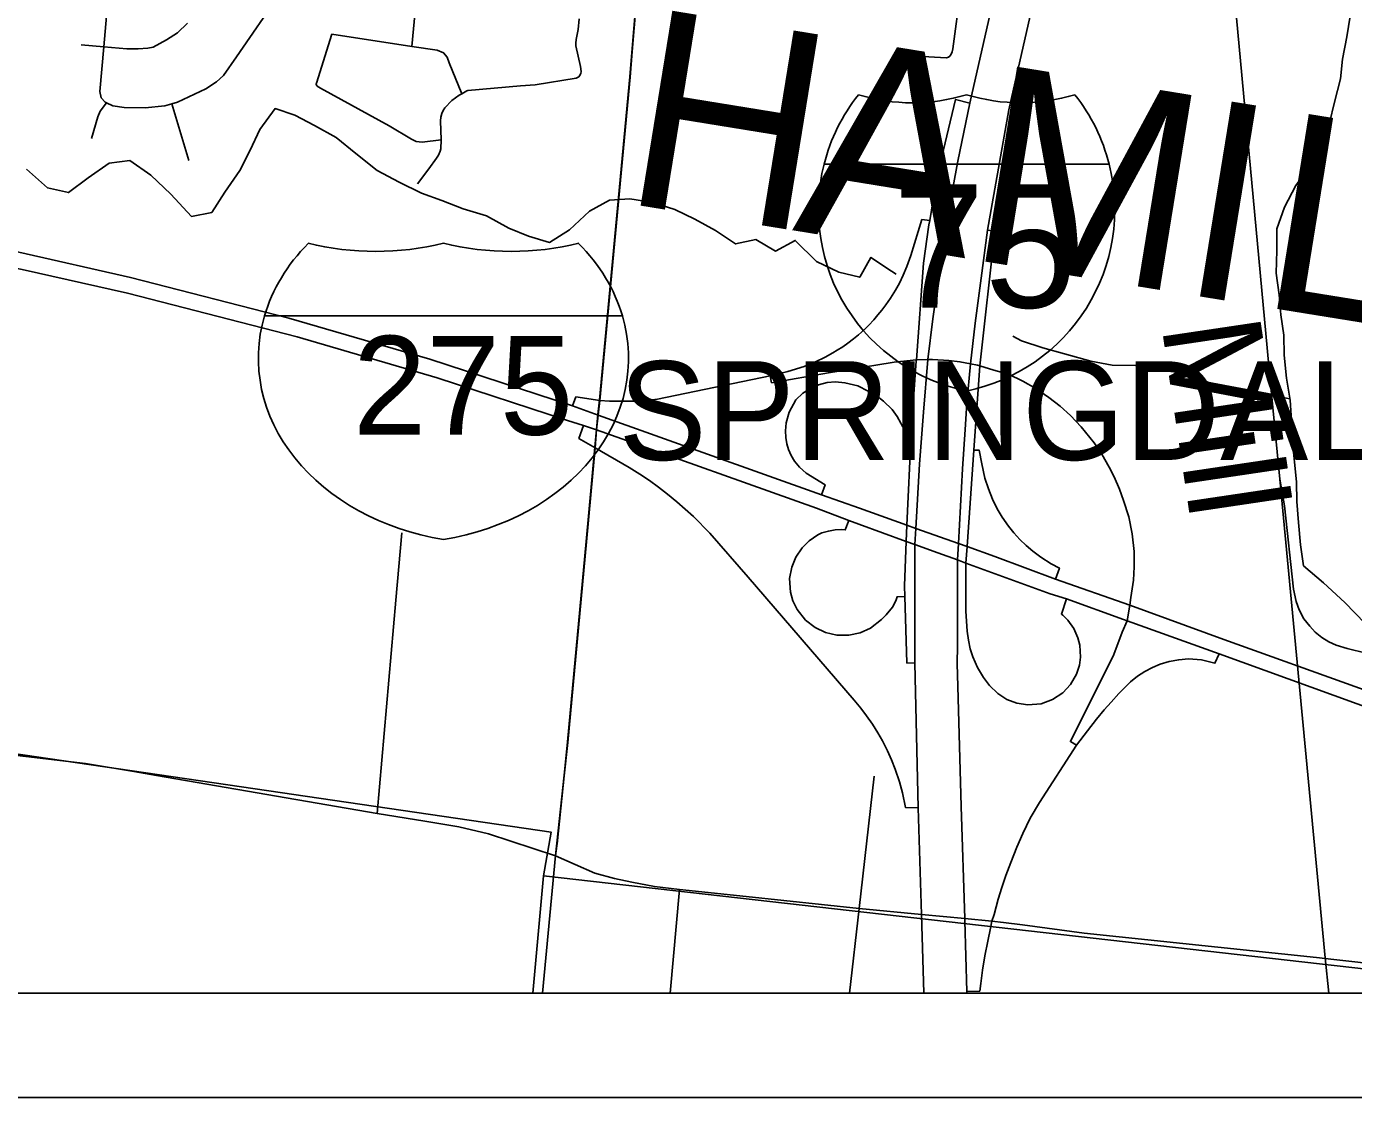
# Model space of a CAD drawing. Extents: x 0 to 34, y 0 to 22.
# Drawn here: x 4.792 to 6.065, y 14 to 15.027 of the extents above; entities that cross this region are included whole.
import ezdxf

# ---------------------------------------------------------------- set-up
doc = ezdxf.new("R2010")
doc.units = 0
for name, color, linetype in [('Default', 7, 'Continuous'), ('GM_X_City_Street', 7, 'Continuous'), ('GM_X_Corporation_Text', 7, 'Continuous'), ('GM_X_County_Road', 7, 'Continuous'), ('GM_X_County_Text', 7, 'Continuous'), ('GM_X_Interchange_Ramps', 7, 'Continuous'), ('GM_X_Interstate_Location', 7, 'Continuous'), ('GM_X_Interstate_Route', 7, 'Continuous'), ('GM_X_Interstate_Shield', 7, 'Continuous'), ('GM_X_Minor_River', 7, 'Continuous'), ('GM_X_Minor_River_Text', 7, 'Continuous'), ('GM_X_Rail_Line', 7, 'Continuous'), ('GM_X_Township_Road', 7, 'Continuous'), ('SH_Cut_Line', 7, 'Continuous'), ('SH_Data', 7, 'Continuous')]:
    doc.layers.add(name, color=color, linetype=linetype)

msp = doc.modelspace()

# ---------------------------------------------------------------- linework, layer by layer
at = {"layer": 'Default'}
for points in [[(4.2792, 14.1), (5.2778, 14.1), (5.2881, 14.2126), (5.2952, 14.2546), (4.3078, 14.3989)], [(5.2778, 14.1), (6.2802, 14.1), (5.2881, 14.2126)]]:
    msp.add_lwpolyline(points, close=True, dxfattribs=at)
at = {"layer": 'GM_X_City_Street'}
for p, q in [((4.9478, 14.8986), (4.9314, 14.9531)), ((5.5906, 14.1811), (5.6049, 14.3083)), ((5.2996, 14.2316), (5.3008, 14.2414)), ((5.4093, 14.1), (5.4184, 14.1996))]:
    msp.add_line(p, q, dxfattribs=at)
for points in [[(5.1618, 15.0081), (5.1671, 15.066), (5.1722, 15.1214), (5.1787, 15.1925), (5.1787, 15.1973), (5.1785, 15.2015), (5.1775, 15.2101), (5.1705, 15.2357), (5.1703, 15.237), (5.1706, 15.2403), (5.1711, 15.2453), (5.1719, 15.256), (5.1742, 15.2989)], [(5.3731, 15.0032), (5.3809, 15.0981), (5.3964, 15.26)], [(5.646, 14.9986), (5.6743, 14.9972), (5.6762, 14.9977), (5.6776, 14.9988), (5.6788, 15.0006), (5.6798, 15.003), (5.6805, 15.0059), (5.6879, 15.0612), (5.6884, 15.0649), (5.7015, 15.2083)], [(4.8817, 15.1847), (4.8662, 15.0077), (4.8625, 14.9647), (4.8637, 14.9589), (4.8677, 14.9546), (4.8689, 14.954), (4.8748, 14.9512), (4.8857, 14.9496), (4.9059, 14.9491), (4.9248, 14.9512), (4.9314, 14.9531), (4.9369, 14.9546), (4.964, 14.9675), (4.9744, 14.974), (4.9812, 14.9801), (4.9934, 14.9982), (5.0353, 15.0592)], [(4.8446, 15.0096), (4.8662, 15.0077), (4.8885, 15.0058), (4.8991, 15.0057), (4.9085, 15.0063), (4.9136, 15.0074), (4.9265, 15.0144), (4.937, 15.0212), (4.9467, 15.0305)], [(5.1671, 14.8763), (5.178, 14.8906), (5.1853, 14.901), (5.1873, 14.9039), (5.1888, 14.9075), (5.1895, 14.9099), (5.1898, 14.9186), (5.1891, 14.9366), (5.1895, 14.9401), (5.1905, 14.9437), (5.1918, 14.9466), (5.1934, 14.9493), (5.2002, 14.9562), (5.2072, 14.9612), (5.2096, 14.9627), (5.2143, 14.9656), (5.2154, 14.9658), (5.2659, 14.9702), (5.2798, 14.9714), (5.3193, 14.9775), (5.3217, 14.9789), (5.3225, 14.98), (5.3236, 14.9821), (5.324, 14.984), (5.3235, 14.9889), (5.319, 15.0085), (5.3189, 15.0112), (5.3193, 15.0146), (5.3212, 15.0244), (5.3222, 15.0346)], [(5.0851, 15.0197), (5.0702, 14.9729), (5.0701, 14.9721), (5.0701, 14.9715), (5.0705, 14.9706), (5.071, 14.97), (5.0742, 14.9681), (5.1399, 14.9318), (5.1614, 14.9191), (5.1658, 14.917), (5.1688, 14.9165), (5.1715, 14.9164), (5.1898, 14.9186)], [(5.2096, 14.9627), (5.1975, 14.9925), (5.1955, 14.9979), (5.1922, 15.0018), (5.1859, 15.0044), (5.1618, 15.0081), (5.0851, 15.0197)], [(5.3008, 14.2414), (5.301, 14.2434), (5.3079, 14.3086), (5.3112, 14.3404), (5.3291, 14.5328), (5.3374, 14.6232), (5.3389, 14.6402), (5.3404, 14.6544), (5.3419, 14.6686), (5.371, 14.9785), (5.3731, 15.0032)], [(4.8545, 14.9198), (4.8607, 14.9404), (4.8628, 14.946), (4.8689, 14.954)], [(5.1285, 14.2725), (5.1465, 14.4771), (5.1521, 14.5415)]]:
    msp.add_lwpolyline(points, dxfattribs=at)
at = {"layer": 'GM_X_County_Road'}
msp.add_line((5.5815, 14.1), (5.5906, 14.1811), dxfattribs=at)
for points in [[(4.3126, 14.3982), (4.3626, 14.3925), (4.4829, 14.374), (4.6768, 14.3406), (4.8489, 14.3202), (4.8951, 14.3126), (4.9168, 14.3089)], [(4.9168, 14.3089), (5.1285, 14.2725), (5.174, 14.2651)], [(5.174, 14.2651), (5.2067, 14.2597), (5.2353, 14.2528), (5.2996, 14.2316)], [(5.2996, 14.2316), (5.3373, 14.2152), (5.3561, 14.21), (5.3727, 14.2065), (5.3944, 14.2022), (5.4184, 14.1996), (5.4824, 14.1927)], [(5.4824, 14.1927), (5.5906, 14.1811), (5.6503, 14.1754), (5.6919, 14.1715), (5.718, 14.169), (5.7291, 14.1677)], [(5.7291, 14.1677), (5.7472, 14.1655), (5.8064, 14.1576), (6.0291, 14.1343), (6.0458, 14.1324)], [(6.0458, 14.1324), (6.1431, 14.1216), (6.196, 14.1114), (6.2535, 14.1)]]:
    msp.add_lwpolyline(points, dxfattribs=at)
at = {"layer": 'GM_X_Interchange_Ramps'}
msp.add_line((5.3188, 14.6721), (5.3158, 14.6634), dxfattribs=at)
for points in [[(5.6968, 14.9536), (5.6831, 14.9572), (5.6647, 14.8809), (5.6583, 14.8412)], [(5.6583, 14.8412), (5.6509, 14.842), (5.6401, 14.8077), (5.6363, 14.797), (5.6329, 14.7887), (5.6292, 14.7811), (5.6255, 14.7744), (5.6208, 14.7667), (5.6162, 14.7601), (5.6124, 14.755), (5.6087, 14.7505), (5.6046, 14.7457), (5.5998, 14.7407), (5.5957, 14.7367), (5.5899, 14.7315), (5.5853, 14.7277), (5.5798, 14.7235), (5.575, 14.7201), (5.5696, 14.7166), (5.5655, 14.7141), (5.558, 14.71), (5.5487, 14.7055), (5.5379, 14.7012), (5.5222, 14.6962), (5.5052, 14.6921)], [(5.6583, 14.8412), (5.6576, 14.837), (5.6522, 14.8002), (5.6455, 14.7074), (5.6454, 14.7066), (5.6408, 14.6427)], [(5.7005, 14.621), (5.7064, 14.7016), (5.7207, 14.831), (5.7137, 14.832)], [(5.6068, 14.7025), (5.5611, 14.6951), (5.5067, 14.6855), (5.5052, 14.6921)], [(5.799, 14.3378), (5.7933, 14.3414), (5.835, 14.4248), (5.8428, 14.4462), (5.8476, 14.457), (5.8501, 14.4721), (5.8513, 14.4794), (5.8538, 14.496), (5.8543, 14.5088), (5.8544, 14.5236), (5.8526, 14.5405), (5.8492, 14.5568), (5.844, 14.5725), (5.8402, 14.5833), (5.8351, 14.5954), (5.8305, 14.6047), (5.8235, 14.6169), (5.8161, 14.6279), (5.8037, 14.6433), (5.7934, 14.6541), (5.7835, 14.663), (5.7727, 14.6715), (5.7602, 14.6799), (5.7475, 14.6871), (5.7339, 14.6936), (5.7199, 14.6977), (5.7064, 14.7016), (5.704, 14.7023), (5.6973, 14.7036), (5.6872, 14.7056), (5.6766, 14.7068), (5.6609, 14.7078), (5.6564, 14.7077), (5.6455, 14.7074), (5.6241, 14.7053), (5.6068, 14.7025)], [(5.5052, 14.6921), (5.3973, 14.6698), (5.3895, 14.6689), (5.3828, 14.6684), (5.376, 14.668), (5.3701, 14.6678), (5.3648, 14.6677), (5.3579, 14.6677), (5.3514, 14.6679), (5.3419, 14.6686), (5.3188, 14.6721)], [(5.5546, 14.5781), (5.5582, 14.5875), (5.5397, 14.5988), (5.5333, 14.6046), (5.5288, 14.6102), (5.5256, 14.6156), (5.523, 14.6215), (5.5213, 14.627), (5.5202, 14.6331), (5.5199, 14.6393), (5.5206, 14.647), (5.5234, 14.6572), (5.53, 14.6691), (5.5368, 14.6755), (5.5439, 14.6801), (5.5517, 14.6835), (5.5601, 14.6856), (5.568, 14.6863), (5.577, 14.6855), (5.5893, 14.6824), (5.5992, 14.6775), (5.6065, 14.6736), (5.6141, 14.668), (5.6223, 14.6598), (5.6271, 14.6532), (5.6307, 14.6467), (5.6321, 14.6434), (5.6408, 14.6427)], [(5.3264, 14.6445), (5.3219, 14.6321), (5.3374, 14.6232)], [(5.6408, 14.6427), (5.6404, 14.6373), (5.6365, 14.5488), (5.6358, 14.5334), (5.6341, 14.4908), (5.6344, 14.4805)], [(5.3374, 14.6232), (5.37, 14.6043), (5.3803, 14.5979), (5.3895, 14.5917), (5.3983, 14.5853), (5.407, 14.5787), (5.4158, 14.5714), (5.4239, 14.5644), (5.4317, 14.5571), (5.4473, 14.5413), (5.4841, 14.4989)], [(5.7894, 14.4781), (5.7846, 14.4637), (5.7859, 14.4627), (5.7908, 14.4577), (5.7965, 14.4499), (5.8005, 14.441), (5.8024, 14.4337), (5.803, 14.4222), (5.8019, 14.4145), (5.7992, 14.406), (5.7934, 14.3961), (5.786, 14.3882), (5.776, 14.3816), (5.7652, 14.3777), (5.7524, 14.3765), (5.742, 14.3781), (5.7324, 14.3817), (5.7236, 14.3874), (5.7158, 14.3952), (5.71, 14.4027), (5.7041, 14.4125), (5.6996, 14.4227), (5.6972, 14.4302), (5.6954, 14.4386), (5.6943, 14.4474), (5.693, 14.4664), (5.693, 14.5124), (5.6941, 14.5286), (5.7005, 14.621)], [(5.7788, 14.4971), (5.7827, 14.5077), (5.7749, 14.5118), (5.7648, 14.5181), (5.7571, 14.5239), (5.7507, 14.5294), (5.7448, 14.5351), (5.7389, 14.5416), (5.7338, 14.548), (5.7277, 14.5567), (5.7231, 14.5646), (5.7185, 14.5738), (5.7146, 14.5836), (5.7113, 14.5941), (5.7083, 14.6076), (5.7058, 14.6207), (5.7005, 14.621)], [(5.6344, 14.4805), (5.627, 14.4803), (5.6259, 14.4764), (5.6227, 14.4704), (5.6167, 14.463), (5.612, 14.4583), (5.6014, 14.4502), (5.5917, 14.4458), (5.5806, 14.4434), (5.5691, 14.4435), (5.5584, 14.4459), (5.5484, 14.4507), (5.5393, 14.4578), (5.5312, 14.4681), (5.5272, 14.4762), (5.5248, 14.4845), (5.524, 14.4976), (5.526, 14.5086), (5.5299, 14.5183), (5.5359, 14.5273), (5.5426, 14.534), (5.5509, 14.5396), (5.5549, 14.5416), (5.5611, 14.5433), (5.5676, 14.5443), (5.5737, 14.5446), (5.5773, 14.5443), (5.5808, 14.5533)], [(5.4841, 14.4989), (5.5859, 14.3812), (5.5924, 14.3733), (5.5978, 14.3661), (5.6034, 14.358), (5.6086, 14.3497), (5.6129, 14.3421), (5.6177, 14.3326), (5.6216, 14.3239), (5.6251, 14.3149), (5.6292, 14.3026), (5.6322, 14.2921), (5.635, 14.2782), (5.6474, 14.2779)], [(5.6344, 14.4805), (5.6363, 14.4168), (5.6439, 14.4167)], [(5.799, 14.3378), (5.8095, 14.3517), (5.8182, 14.3628), (5.8257, 14.3717), (5.8324, 14.3793), (5.8398, 14.3874), (5.851, 14.3986), (5.8577, 14.404), (5.8645, 14.4085), (5.8721, 14.4125), (5.8792, 14.4155), (5.888, 14.4182), (5.8972, 14.4199), (5.9064, 14.4207), (5.9191, 14.4197), (5.9318, 14.4165), (5.9359, 14.4255)], [(5.6938, 14.1017), (5.7063, 14.102), (5.7072, 14.1093), (5.7089, 14.1222), (5.7112, 14.1358), (5.7139, 14.1499), (5.7166, 14.1623), (5.718, 14.169), (5.72, 14.1756), (5.724, 14.1901), (5.7276, 14.2015), (5.7314, 14.2129), (5.736, 14.2254), (5.742, 14.2402), (5.7476, 14.2531), (5.7547, 14.268), (5.7635, 14.2828), (5.799, 14.3378)]]:
    msp.add_lwpolyline(points, dxfattribs=at)
at = {"layer": 'GM_X_Interstate_Route'}
for p, q in [((5.737, 14.96), (5.7593, 15.0581)), ((5.6849, 14.4336), (5.6851, 14.5117))]:
    msp.add_line(p, q, dxfattribs=at)
for points in [[(5.6527, 14.1), (5.6527, 14.1005), (5.6503, 14.1754), (5.6474, 14.2779), (5.6439, 14.4167), (5.6442, 14.5303), (5.6451, 14.5458), (5.6485, 14.6074), (5.6523, 14.6572), (5.6564, 14.7077), (5.6613, 14.7467), (5.6689, 14.8013), (5.6768, 14.8515), (5.6854, 14.898), (5.6968, 14.9536), (5.7231, 15.0694), (5.7592, 15.1991)], [(5.6851, 14.5117), (5.6851, 14.5156), (5.686, 14.5313), (5.6897, 14.6031), (5.6923, 14.6408), (5.694, 14.666), (5.6973, 14.7036), (5.7019, 14.7427), (5.7075, 14.7858), (5.7137, 14.832), (5.7251, 14.8968), (5.7341, 14.9472), (5.737, 14.96)], [(3.431, 14.9265), (3.5922, 14.9215), (3.7836, 14.9152), (3.9522, 14.9113), (4.1018, 14.9036), (4.184, 14.8973), (4.282, 14.8887), (4.3496, 14.8808), (4.3592, 14.8798), (4.4684, 14.865), (4.6643, 14.8337), (4.7847, 14.8106), (4.8918, 14.7863), (5.0436, 14.7475), (5.1791, 14.7082), (5.3158, 14.6634)], [(4.6141, 14.8262), (4.6644, 14.8177), (4.7879, 14.7942), (4.889, 14.7714), (5.0516, 14.7297), (5.186, 14.6902), (5.311, 14.6492), (5.3264, 14.6445), (5.3389, 14.6402), (5.3488, 14.6367)], [(5.3158, 14.6634), (5.3404, 14.6544), (5.5546, 14.5781), (5.5911, 14.5652), (5.6365, 14.5488), (5.6451, 14.5458), (5.686, 14.5313), (5.6941, 14.5286), (5.7207, 14.5188), (5.7788, 14.4971), (5.8501, 14.4721), (5.9404, 14.4394), (6.3306, 14.2992)], [(5.3488, 14.6367), (5.5496, 14.5652), (5.5808, 14.5533), (5.5903, 14.5499)], [(5.5903, 14.5499), (5.6358, 14.5334), (5.6442, 14.5303), (5.6661, 14.5225)], [(5.6661, 14.5225), (5.6851, 14.5156), (5.693, 14.5124), (5.7739, 14.4832), (5.7894, 14.4781), (5.844, 14.4583)], [(5.844, 14.4583), (5.8476, 14.457), (5.9359, 14.4255), (6.3293, 14.2829)], [(5.6854, 14.3945), (5.6848, 14.416), (5.6849, 14.4336)], [(5.6919, 14.1695), (5.6919, 14.1715), (5.6886, 14.2791), (5.6854, 14.3945)], [(5.6939, 14.1), (5.6938, 14.1017), (5.6919, 14.1695)]]:
    msp.add_lwpolyline(points, dxfattribs=at)
at = {"layer": 'GM_X_Interstate_Shield'}
for p, q in [((5.557, 14.8952), (5.8303, 14.8952)), ((5.8303, 14.8952), (5.557, 14.8952)), ((5.8303, 14.8952), (5.557, 14.8952)), ((5.3637, 14.7496), (5.0203, 14.7496)), ((5.3637, 14.7496), (5.0203, 14.7496))]:
    msp.add_line(p, q, dxfattribs=at)
for centre, start, end in [((5.7292, 14.8516), 141.669, 165.8066), ((5.6418, 15.1316), 253.0091, 286.9909), ((5.7456, 15.1316), 253.0091, 286.9909), ((5.6582, 14.8516), 14.1934, 38.331), ((5.7292, 14.8516), 165.8066, 258.463), ((5.6582, 14.8516), 281.537, 14.1934)]:
    msp.add_arc(centre, 0.1776, start, end, dxfattribs=at)
for centre, start_param, end_param in [((5.2364, 14.7091), 2.47259, 2.911027), ((5.1271, 14.989), 4.415841, 5.008937), ((5.2569, 14.989), 4.415841, 5.008937), ((5.1476, 14.7091), 0.230566, 0.669003), ((5.2364, 14.7091), 2.911027, 4.511031), ((5.1476, 14.7091), 4.913747, 6.513751)]:
    msp.add_ellipse(centre, major_axis=(0.2219, 0), ratio=0.8, start_param=start_param, end_param=end_param, dxfattribs=at)
at = {"layer": 'GM_X_Minor_River'}
for points in [[(6.0758, 14.4545), (6.0564, 14.4747), (6.0359, 14.4936), (6.0169, 14.51), (6.0139, 14.5301), (6.012, 14.5514), (6.0105, 14.5715), (6.0101, 14.5905), (6.0082, 14.6094), (6.0063, 14.6284), (6.0052, 14.6489), (6.004, 14.6687), (6.0006, 14.6899), (5.9983, 14.712), (5.998, 14.7313), (5.9949, 14.7507), (5.9934, 14.7697), (5.9907, 14.7905), (5.9911, 14.8122), (5.9911, 14.8331), (5.9987, 14.8539), (6.0093, 14.8748), (6.0234, 14.8946), (6.0367, 14.9155), (6.0416, 14.9348), (6.0466, 14.9546), (6.0522, 14.977), (6.0541, 14.996), (6.0583, 15.0172), (6.0614, 15.037)], [(5.6263, 14.7895), (5.6217, 14.7924), (5.602, 14.8057), (5.5913, 14.7867), (5.5712, 14.7916), (5.5499, 14.8019), (5.5294, 14.822), (5.5105, 14.8118), (5.4915, 14.8228), (5.4721, 14.8186), (5.4528, 14.8315), (5.433, 14.8425), (5.414, 14.8516), (5.3928, 14.8585), (5.3707, 14.8619), (5.3514, 14.8607), (5.332, 14.8501), (5.313, 14.8323), (5.2937, 14.8201), (5.2735, 14.8262), (5.2546, 14.8338), (5.2333, 14.8455), (5.2109, 14.8524), (5.1904, 14.8603), (5.171, 14.8672), (5.1494, 14.8778), (5.1285, 14.8892), (5.108, 14.9055), (5.089, 14.9207), (5.0685, 14.9321), (5.0495, 14.9423), (5.0306, 14.9484), (5.0158, 14.9283), (5.0066, 14.9085), (4.9968, 14.8892), (4.9823, 14.8683), (4.9698, 14.8489), (4.9505, 14.8451), (4.9307, 14.8664), (4.9114, 14.8846), (4.8912, 14.8987), (4.8715, 14.896), (4.8514, 14.882), (4.8324, 14.8679), (4.8123, 14.8725), (4.7921, 14.8903)], [(6.0038, 14.67), (5.9843, 14.674), (5.963, 14.6747), (5.9433, 14.6789), (5.9201, 14.688), (5.9011, 14.6941), (5.8795, 14.6998), (5.8556, 14.7021), (5.8332, 14.7024), (5.8127, 14.7062), (5.7876, 14.7131), (5.7667, 14.7191), (5.7462, 14.7256), (5.738, 14.7303)]]:
    msp.add_lwpolyline(points, dxfattribs=at)
at = {"layer": 'GM_X_Rail_Line'}
for points in [[(6.0409, 14.1), (6.0376, 14.1338), (5.9941, 14.593), (5.9848, 14.6879), (5.9482, 15.0807), (5.9387, 15.161)], [(5.9941, 14.593), (5.9986, 14.5675), (6.0072, 14.4874), (6.0098, 14.4757), (6.0126, 14.4678), (6.0172, 14.4592), (6.0228, 14.4519), (6.028, 14.4463), (6.0345, 14.4411), (6.041, 14.4369), (6.048, 14.4339), (6.0587, 14.4307), (6.095, 14.4217)]]:
    msp.add_lwpolyline(points, dxfattribs=at)
at = {"layer": 'GM_X_Township_Road'}
for points in [[(2.1, 14.1), (5.2869, 14.1), (5.2994, 14.2321), (5.3008, 14.2439), (5.3077, 14.3092), (5.311, 14.341), (5.3288, 14.5334), (5.3372, 14.6237), (5.3387, 14.6408), (5.3402, 14.6549), (5.3417, 14.6691), (5.3708, 14.979), (5.3806, 15.0986), (5.3962, 15.2605), (5.26, 15.2853), (5.174, 15.2994), (5.0019, 15.3285), (4.9347, 15.3398), (4.7447, 15.3727), (4.5421, 15.4075), (4.4074, 15.4288), (3.9247, 15.3988), (3.4976, 15.3675), (3.3845, 15.362)], [(6.3032, 15.1064), (5.9659, 15.1626), (5.7963, 15.1933), (5.759, 15.1996), (5.7013, 15.2088), (5.5712, 15.2317), (5.3962, 15.2605), (5.3806, 15.0986), (5.3708, 14.979), (5.3417, 14.6691), (5.3402, 14.6549), (5.3387, 14.6408), (5.3372, 14.6237), (5.3288, 14.5334), (5.311, 14.341), (5.3077, 14.3092), (5.3008, 14.2439), (5.2994, 14.2321), (5.2869, 14.1), (8.9, 14.1)]]:
    msp.add_lwpolyline(points, dxfattribs=at)
at = {"layer": 'SH_Cut_Line'}
msp.add_lwpolyline([(2.1, 14.1), (8.9, 14.1)], dxfattribs=at)
at = {"layer": 'SH_Data'}
for p, q in [((2.1, 14.1), (8.9, 14.1)), ((2, 14), (9, 14))]:
    msp.add_line(p, q, dxfattribs=at)

# ---------------------------------------------------------------- texts
at = {"layer": 'GM_X_Corporation_Text'}
msp.add_text('SPRINGDALE', height=0.0947, rotation=0, dxfattribs=at).set_placement((5.3599, 14.6115))
at = {"layer": 'GM_X_County_Text'}
for s, rotation, p in [('H', 350.7711, (5.3606, 14.8587)), ('A', 350.7706, (5.5259, 14.8319)), ('M', 350.7728, (5.6912, 14.805)), ('I', 350.7835, (5.8945, 14.772)), ('L', 350.8157, (5.9711, 14.7596))]:
    msp.add_text(s, height=0.1894, rotation=rotation, dxfattribs=at).set_placement(p)
at = {"layer": 'GM_X_Interstate_Location'}
for s, p in [('.', (5.6936, 14.8196)), ('-', (5.6936, 14.8196)), (',', (5.6936, 14.8196)), ('.', (5.192, 14.683)), ('-', (5.192, 14.683)), (',', (5.192, 14.683))]:
    msp.add_text(s, height=0.000189, dxfattribs=at).set_placement(p)
for s, p in [('75', (5.6549, 14.7804)), ('275', (5.1341, 14.6438))]:
    msp.add_text(s, height=0.000189, rotation=0, dxfattribs=at).set_placement(p)
at = {"layer": 'GM_X_Interstate_Shield'}
for s, height, p in [('75', 0.11837, (5.623, 14.7576)), ('275', 0.0947, (5.1052, 14.6357))]:
    msp.add_text(s, height=height, dxfattribs=at).set_placement(p)
at = {"layer": 'GM_X_Minor_River_Text'}
msp.add_text('Mill', height=0.0947, rotation=278.467, dxfattribs=at).set_placement((5.8805, 14.7403))

doc.saveas('drawing.dxf')
